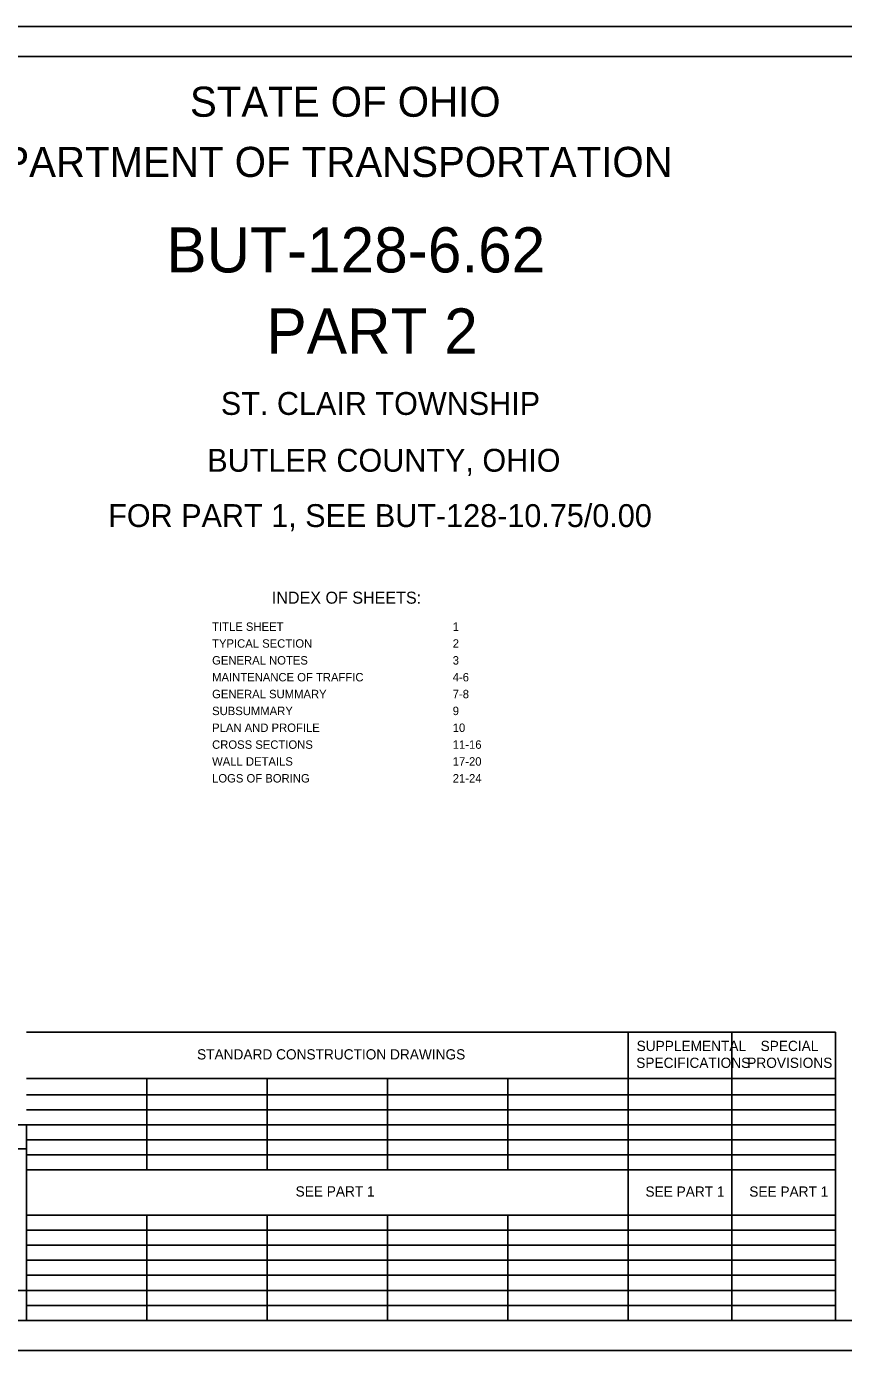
# Model space of a CAD drawing. Extents: x 0 to 45, y -99 to 22.
# Drawn here: x 11.25 to 24.83, y 0 to 22 of the extents above; entities that cross this region are included whole.
import ezdxf

# ---------------------------------------------------------------- set-up
doc = ezdxf.new("R2010")
doc.units = 0
for name, color, linetype in [('Default', 7, 'Continuous'), ('SH_Border', 7, 'Continuous'), ('SH_Cut_Line', 7, 'Continuous'), ('SH_Data', 7, 'Continuous'), ('SH_Text', 7, 'Continuous')]:
    doc.layers.add(name, color=color, linetype=linetype)

msp = doc.modelspace()

# ---------------------------------------------------------------- linework, layer by layer
at = {"layer": 'SH_Border'}
msp.add_lwpolyline([(1.5, 21.5), (33.5, 21.5), (33.5, 0.5), (1.5, 0.5)], close=True, dxfattribs=at)
at = {"layer": 'SH_Cut_Line'}
for p, q in [((11.25, 5.292), (24.7, 5.292)), ((21.25, 0.5), (21.25, 5.292)), ((22.975, 0.5), (22.975, 5.292)), ((24.7, 0.5), (24.7, 5.292)), ((11.25, 4.521), (24.7, 4.521)), ((13.25, 3), (13.25, 4.521)), ((15.25, 3), (15.25, 4.521)), ((17.25, 3), (17.25, 4.521)), ((19.25, 3), (19.25, 4.521)), ((11.25, 4.25), (24.7, 4.25)), ((11.25, 4), (24.7, 4)), ((11.251, 3.75), (8.451, 3.75)), ((11.25, 3.75), (24.7, 3.75)), ((11.251, 0.5), (11.251, 3.75)), ((11.251, 3.35), (8.451, 3.35)), ((11.25, 3.5), (24.7, 3.5)), ((11.25, 3.25), (24.7, 3.25)), ((11.25, 3), (24.7, 3)), ((11.25, 2.25), (24.7, 2.25)), ((13.25, 0.5), (13.25, 2.25)), ((15.25, 0.5), (15.25, 2.25)), ((17.25, 0.5), (17.25, 2.25)), ((19.25, 0.5), (19.25, 2.25)), ((11.25, 2), (24.7, 2)), ((11.25, 1.75), (24.7, 1.75)), ((11.25, 1.5), (24.7, 1.5)), ((11.25, 1.25), (24.7, 1.25)), ((11.25, 1), (24.7, 1)), ((11.25, 0.75), (24.7, 0.75)), ((11.251, 0.5), (8.451, 0.5))]:
    msp.add_line(p, q, dxfattribs=at)
msp.add_lwpolyline([(11.251, 0.5), (11.251, 1), (8.451, 1), (8.451, 0.5)], close=True, dxfattribs=at)
at = {"layer": 'SH_Data'}
msp.add_lwpolyline([(0, 0), (34, 0), (34, 22), (0, 22)], close=True, dxfattribs=at)

# ---------------------------------------------------------------- texts
at = {"layer": 'Default'}
for p in [(15.724, 2.559), (21.54, 2.556), (23.266, 2.556)]:
    msp.add_text('SEE PART 1', height=0.17, dxfattribs=at).set_placement(p)
at = {"layer": 'SH_Text'}
for s, height, p in [('STATE OF OHIO', 0.5, (13.968, 20.5)), ('DEPARTMENT OF TRANSPORTATION', 0.5, (9.92, 19.5)), ('BUT-128-6.62', 0.75, (13.575, 17.913)), ('   PART 2   ', 0.75, (14.405, 16.566)), (' ST. CLAIR TOWNSHIP ', 0.38, (14.34, 15.546)), (' BUTLER COUNTY, OHIO', 0.38, (14.114, 14.602)), ('      FOR PART 1, SEE BUT-128-10.75/0.00     ', 0.38, (11.761, 13.683)), ('INDEX OF SHEETS:', 0.2, (15.329, 12.409)), ('TITLE SHEET', 0.14, (14.336, 11.958)), ('1', 0.14, (18.336, 11.958)), ('TYPICAL SECTION', 0.14, (14.336, 11.678)), ('2', 0.14, (18.336, 11.678)), ('GENERAL NOTES', 0.14, (14.336, 11.398)), ('3', 0.14, (18.336, 11.398)), ('MAINTENANCE OF TRAFFIC', 0.14, (14.336, 11.118)), ('4-6', 0.14, (18.336, 11.118)), ('GENERAL SUMMARY', 0.14, (14.336, 10.838)), ('7-8', 0.14, (18.336, 10.838)), ('SUBSUMMARY', 0.14, (14.336, 10.558)), ('9', 0.14, (18.336, 10.558)), ('PLAN AND PROFILE', 0.14, (14.336, 10.278)), ('10', 0.14, (18.336, 10.278)), ('CROSS SECTIONS', 0.14, (14.336, 9.998)), ('11-16', 0.14, (18.336, 9.998)), ('WALL DETAILS', 0.14, (14.336, 9.718)), ('17-20', 0.14, (18.336, 9.718)), ('LOGS OF BORING', 0.14, (14.336, 9.438)), ('21-24  ', 0.14, (18.336, 9.438)), ('SUPPLEMENTAL', 0.17, (21.393, 4.976)), ('SPECIAL', 0.17, (23.454, 4.976)), ('STANDARD CONSTRUCTION DRAWINGS', 0.17, (14.086, 4.836)), ('SPECIFICATIONS', 0.17, (21.387, 4.696)), ('PROVISIONS', 0.17, (23.232, 4.696))]:
    msp.add_text(s, height=height, dxfattribs=at).set_placement(p)

doc.saveas('drawing.dxf')
